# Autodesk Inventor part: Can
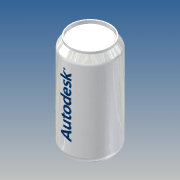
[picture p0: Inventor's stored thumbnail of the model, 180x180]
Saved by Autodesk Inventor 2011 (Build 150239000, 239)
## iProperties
Created: 2008-06
Part Number: Can
Document SubType Name: Modeling
Density: 1 g/cm^3
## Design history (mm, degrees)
sketch "Sketch1"
  geometry: L1 (26.273, -22.486)-(26.273, 85.464); L2 (26.273, 85.464)-(20.571, 94.049); L3 (20.571, 94.049)-(20.571, 97.224); L4 (20.571, 97.224)-(-5.477, 97.224); L5 (-5.477, 97.224)-(-5.477, -43.573); L6 (-5.477, 97.224)-(-5.477, -26.735); L7 (26.273, -22.486)-(22.247, -25.159); L8 (22.247, -25.159)-(22.247, -26.735); L9 (22.247, -26.735)-(-5.477, -26.735)
  constraints: 18 end point, 4 perpendicular, 2 parallel, 2 point on line, 1 vertical
  dimensions: "d0" = 63.5 diameter of L1 L5; "d2" = 107.95 distance of L1.start L1.end; "d5" = 3.175 distance of L2.end L3.end
revolve "Revolution1" sketch "Sketch1" stored, may be unused: angle "d3" = 90 deg
workplane "Work Plane1"
  workaxis "Work Axis1"
sketch "Sketch2"
  geometry: L1 (-1.588, -26.049)-(-1.588, 26.049) reference; L2 (-1.588, 26.049)-(1.588, 26.049) reference; L3 (-1.588, 24.499)-(3.258, 24.499); L4 (3.258, 24.499)-(3.258, 23.037); L5 (3.258, 23.037)-(1.588, 23.037); L6 (-76.977, 0)-(450.75, 0) reference; L7 (1.588, 23.037)-(1.588, 0); L8 (0.835, 0)-(-1.588, 0); L9 (-1.588, 0)-(-1.588, 24.499); A1 r 374.525 centre (375.36, -0.697) between (1.588, 23.037) and (0.835, 0)
  constraints: 12 end point, 4 point on line, 2 parallel, 2 perpendicular, 2 point on circle, 1 centre point, 1 collinear, 1 midpoint
revolve "Revolution2" sketch "Sketch2" stored, may be unused: angle "d6" = 90 deg
sketch "Sketch3"
  geometry: L1 (122.371, -27.725)-(122.371, 27.725) reference; L2 (122.371, -27.725)-(122.371, 27.725) reference; L3 (120.795, -27.725)-(120.795, 27.725) reference; L4 (118.122, 31.75)-(120.795, 27.725) reference; L5 (122.371, 26.406)-(119.02, 26.406); L6 (-26.379, 0)-(147.163, 0) reference; L7 (115.862, 0)-(122.371, 0); L8 (122.371, 0)-(122.371, 26.406); A1 r 108.664 centre (224.525, 0.396) between (119.02, 26.406) and (115.862, 0)
  constraints: 6 end point, 3 point on line, 2 point on circle, 1 centre point, 1 collinear, 1 midpoint, 1 perpendicular
revolve "Revolution3" sketch "Sketch3" stored, may be unused: angle "d7" = 90 deg
fillet "Fillet1" dims "d8" = 6.35
fillet "Fillet2" dims "d9" = 0.508
workplane "Work Plane2"
sketch "Sketch4"
  geometry: L1 (101.713, -10.618)-(16.79, -10.618); L2 (16.79, -10.618)-(16.79, 10.618); L3 (16.79, 10.618)-(101.713, 10.618); L4 (101.713, 10.618)-(101.713, -10.618); L5 (-1.08, 26.049)-(-1.08, -26.049) reference; L6 (-1.08, 0)-(17.418, 0); 1 further point; 1 other entity
  constraints: 2 end point, 2 horizontal, 2 midpoint, 1 horizontal alignment, 2 other
feature "Decal1" sketch "Sketch4"
workaxis "Work Axis2"
body "Solid1"
node "Projected Loop1"
node "Image1"
other parameters: "d4" = 90 deg, "d10" = 39.6875
